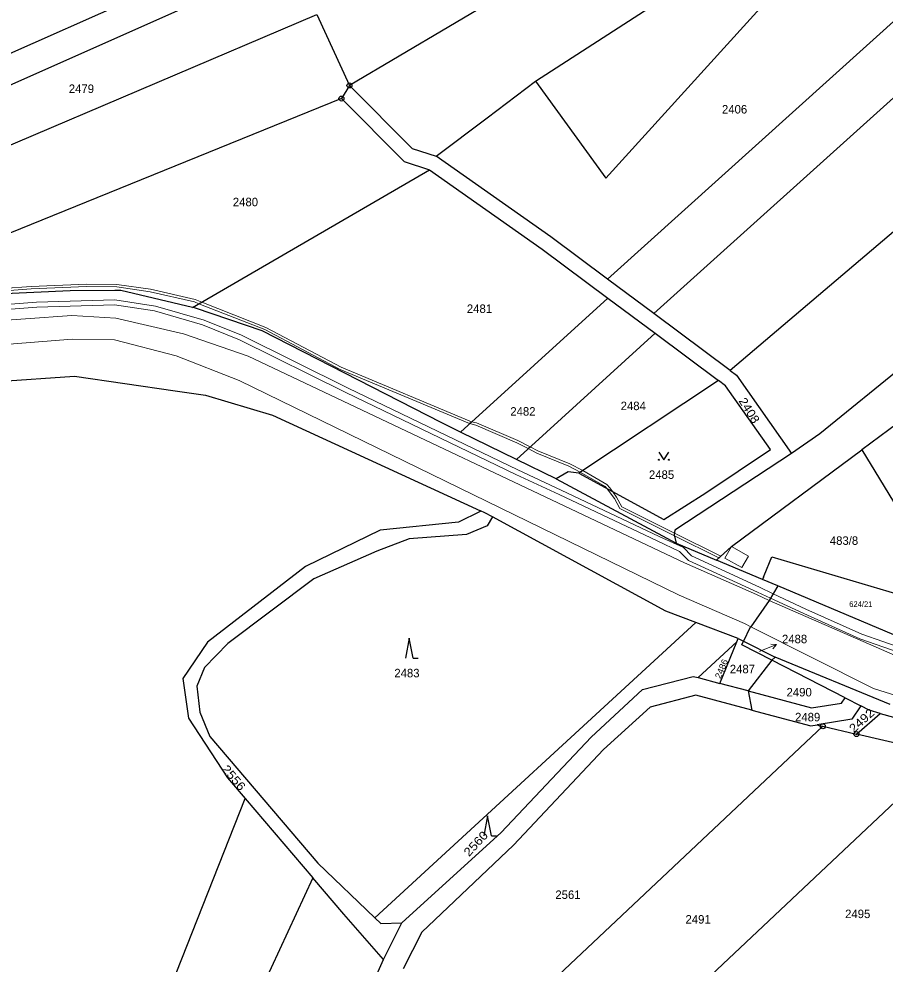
# Model space of a CAD drawing. Extents: x -606517 to -602431, y -1183120 to -1179397.
# Drawn here: x -605001.8 to -604828.2, y -1181046.7 to -1180857.3 of the extents above; entities that cross this region are included whole.
import ezdxf
from ezdxf.enums import TextEntityAlignment as Align

# ---------------------------------------------------------------- set-up
doc = ezdxf.new("R2010")
doc.units = 0
doc.header["$LTSCALE"] = 0.68
for name, color, linetype, lineweight in [('1', 7, 'Continuous', 25), ('13', 7, 'Continuous', 13), ('3', 7, 'Continuous', 25), ('4', 7, 'Continuous', 13), ('7', 7, 'Continuous', 13), ('8', 7, 'Continuous', 25)]:
    doc.layers.add(name, color=color, linetype=linetype, lineweight=lineweight)
doc.layers.add('2', color=7, linetype='Continuous')

msp = doc.modelspace()

# ---------------------------------------------------------------- linework, layer by layer
at = {"layer": '1'}
for p, q in [((-604864.72, -1180828.8), (-604935.53, -1180870.63)), ((-604883.82, -1180909.45), (-604798.46, -1180832.55)), ((-605066.61, -1180892.1), (-604946.99, -1180839.11)), ((-604874.53, -1180916.36), (-604790.07, -1180840.29)), ((-604945.04, -1180844.43), (-605064.46, -1180897.79)), ((-604898.22, -1180869.74), (-604864.02, -1180847.64)), ((-604884.17, -1180889.23), (-604851.96, -1180853.72)), ((-605061.96, -1180907.49), (-604942.1, -1180856.39)), ((-604942.1, -1180856.39), (-604935.53, -1180870.63)), ((-604907.94, -1180877.1), (-604898.22, -1180869.74)), ((-604898.22, -1180869.74), (-604884.17, -1180889.23)), ((-604935.53, -1180870.63), (-604937.14, -1180873.25)), ((-604935.53, -1180870.63), (-604922.99, -1180883.26)), ((-604937.14, -1180873.25), (-605039.85, -1180914.88)), ((-604937.14, -1180873.25), (-604924.6, -1180885.89)), ((-604918.14, -1180884.81), (-604907.94, -1180877.1)), ((-604922.99, -1180883.26), (-604918.14, -1180884.81)), ((-604895.17, -1180901), (-604918.14, -1180884.81)), ((-604924.6, -1180885.89), (-604919.49, -1180887.53)), ((-604966.98, -1180915.13), (-604919.49, -1180887.53)), ((-604919.49, -1180887.53), (-604896.93, -1180903.43)), ((-604812.16, -1180887.79), (-604859.22, -1180927.76)), ((-604883.82, -1180909.45), (-604895.17, -1180901)), ((-604896.93, -1180903.43), (-604883.73, -1180913.25)), ((-604874.53, -1180916.36), (-604883.82, -1180909.45)), ((-604991.55, -1180911.78), (-605019.29, -1180913.13)), ((-604982.55, -1180911.73), (-604991.55, -1180911.78)), ((-604981.39, -1180911.72), (-604982.55, -1180911.73)), ((-604966.98, -1180915.13), (-604981.39, -1180911.72)), ((-604913.3, -1180940.09), (-604883.73, -1180913.25)), ((-604883.73, -1180913.25), (-604874.25, -1180920.31)), ((-604806.84, -1180912.52), (-604841.26, -1180940.43)), ((-604966.4, -1180915.27), (-604966.98, -1180915.13)), ((-604953.06, -1180919.8), (-604966.4, -1180915.27)), ((-604859.22, -1180927.76), (-604874.53, -1180916.36)), ((-604798.64, -1180918.27), (-604832.85, -1180943.64)), ((-604917.16, -1180938.2), (-604953.06, -1180919.8)), ((-604874.25, -1180920.31), (-604902.08, -1180945.57)), ((-604874.25, -1180920.31), (-604861.56, -1180929.75)), ((-605009.45, -1180930.2), (-604990.65, -1180928.92)), ((-604990.65, -1180928.92), (-604970.51, -1180931.82)), ((-604859.22, -1180927.76), (-604857.95, -1180928.7)), ((-604857.95, -1180928.7), (-604846.92, -1180944.41)), ((-604861.56, -1180929.75), (-604889.57, -1180948.36)), ((-604860.13, -1180930.82), (-604861.56, -1180929.75)), ((-604851.14, -1180943.62), (-604860.13, -1180930.82)), ((-604970.51, -1180931.82), (-604964.37, -1180932.7)), ((-604964.37, -1180932.7), (-604950.98, -1180936.72)), ((-604950.98, -1180936.72), (-604909.28, -1180955.9)), ((-604913.3, -1180940.09), (-604917.16, -1180938.2)), ((-604902.08, -1180945.57), (-604913.3, -1180940.09)), ((-604841.26, -1180940.43), (-604846.92, -1180944.41)), ((-604864.12, -1180952.26), (-604851.14, -1180943.62)), ((-604858.98, -1180963.01), (-604832.85, -1180943.64)), ((-604832.85, -1180943.64), (-604824.77, -1180956.82)), ((-604894.13, -1180949.46), (-604902.08, -1180945.57)), ((-604846.92, -1180944.41), (-604870.34, -1180959.77)), ((-604891.7, -1180948.08), (-604894.13, -1180949.46)), ((-604894.13, -1180949.46), (-604870.06, -1180962.35)), ((-604889.57, -1180948.36), (-604891.7, -1180948.08)), ((-604889.57, -1180948.36), (-604872.52, -1180957.6)), ((-604872.52, -1180957.6), (-604864.12, -1180952.26)), ((-604909.35, -1180956.04), (-604913.68, -1180958.16)), ((-604909.28, -1180955.9), (-604909.35, -1180956.04)), ((-604908.42, -1180956.29), (-604909.28, -1180955.9)), ((-604906.89, -1180957.12), (-604908.42, -1180956.29)), ((-604906.89, -1180957.12), (-604907.93, -1180958.9)), ((-604872.09, -1180976), (-604906.89, -1180957.12)), ((-604913.68, -1180958.16), (-604929.38, -1180959.74)), ((-604907.93, -1180958.9), (-604912.09, -1180960.62)), ((-604929.38, -1180959.74), (-604944.32, -1180967.05)), ((-604912.09, -1180960.62), (-604923.56, -1180961.53)), ((-604870.34, -1180959.77), (-604870.42, -1180960.73)), ((-604870.42, -1180960.73), (-604870.06, -1180962.35)), ((-604923.56, -1180961.53), (-604930.03, -1180963.94)), ((-604870.06, -1180962.35), (-604861.98, -1180965.76)), ((-604861.98, -1180965.76), (-604858.98, -1180963.01)), ((-604930.03, -1180963.94), (-604942.7, -1180969.52)), ((-604852.72, -1180969.66), (-604861.98, -1180965.76)), ((-604852.38, -1180968.84), (-604850.83, -1180965.08)), ((-604850.83, -1180965.08), (-604813.29, -1180976.25)), ((-604944.32, -1180967.05), (-604963.99, -1180982.21)), ((-604942.7, -1180969.52), (-604959.95, -1180982.48)), ((-604852.52, -1180969.18), (-604852.72, -1180969.66)), ((-604849.66, -1180970.95), (-604852.72, -1180969.66)), ((-604852.52, -1180969.18), (-604852.38, -1180968.84)), ((-604849.66, -1180970.95), (-604851.38, -1180973.89)), ((-604825.12, -1180981.3), (-604849.66, -1180970.95)), ((-604851.38, -1180973.89), (-604855.08, -1180979.12)), ((-604866.12, -1180978.25), (-604872.09, -1180976)), ((-604866.12, -1180978.25), (-604930.42, -1181037.48)), ((-604857.58, -1180981.47), (-604866.12, -1180978.25)), ((-604855.24, -1180979.35), (-604856.52, -1180982.01)), ((-604855.08, -1180979.12), (-604855.24, -1180979.35)), ((-604857.86, -1180982.17), (-604857.58, -1180981.47)), ((-604857.58, -1180981.47), (-604856.52, -1180982.01)), ((-604963.99, -1180982.21), (-604968.92, -1180989.51)), ((-604959.95, -1180982.48), (-604964.57, -1180987.26)), ((-604865.63, -1180989.32), (-604857.86, -1180982.17)), ((-604861.28, -1180990.48), (-604857.86, -1180982.17)), ((-604856.87, -1180982.75), (-604856.52, -1180982.01)), ((-604850.87, -1180985.83), (-604856.87, -1180982.75)), ((-604856.52, -1180982.01), (-604850.17, -1180985.22)), ((-604850.17, -1180985.22), (-604850.87, -1180985.83)), ((-604827.14, -1180994.71), (-604850.17, -1180985.22)), ((-604964.57, -1180987.26), (-604966.12, -1180991.02)), ((-604850.87, -1180985.83), (-604855.63, -1180991.99)), ((-604836.18, -1180993.39), (-604850.87, -1180985.83)), ((-604968.92, -1180989.51), (-604967.79, -1180997.44)), ((-604876.8, -1180991.7), (-604866.61, -1180989.06)), ((-604866.61, -1180989.06), (-604865.63, -1180989.32)), ((-604865.63, -1180989.32), (-604861.28, -1180990.48)), ((-604966.12, -1180991.02), (-604965.56, -1180996.27)), ((-604855.63, -1180991.99), (-604861.28, -1180990.48)), ((-604887.08, -1181001.22), (-604876.8, -1180991.7)), ((-604866.11, -1180992.82), (-604875.28, -1180995.24)), ((-604854.87, -1180995.81), (-604866.11, -1180992.82)), ((-604855.63, -1180991.99), (-604842.88, -1180995.39)), ((-604855.63, -1180991.99), (-604854.87, -1180995.81)), ((-604875.28, -1180995.24), (-604884.61, -1181003.71)), ((-604842.88, -1180995.39), (-604836.89, -1180994.45)), ((-604836.89, -1180994.45), (-604836.18, -1180993.39)), ((-604836.18, -1180993.39), (-604833.05, -1180995)), ((-604833.05, -1180995), (-604834.83, -1180997.67)), ((-604831.37, -1180995.86), (-604833.05, -1180995)), ((-604965.56, -1180996.27), (-604963.5, -1181001.09)), ((-604854.87, -1180995.81), (-604843.07, -1180998.96)), ((-604833.9, -1181000.64), (-604829.17, -1180996.48)), ((-604829.17, -1180996.48), (-604831.37, -1180995.86)), ((-604829.17, -1180996.48), (-604803.37, -1181003.79)), ((-604967.79, -1180997.44), (-604959.98, -1181009.37)), ((-604843.07, -1180998.96), (-604841.8, -1180998.76)), ((-604834.83, -1180997.67), (-604841.8, -1180998.76)), ((-604841.8, -1180998.76), (-604841.43, -1180998.89)), ((-604841.43, -1180998.89), (-604840.66, -1180999.07)), ((-604947.06, -1181099.25), (-604840.66, -1180999.07)), ((-604840.66, -1180999.07), (-604833.9, -1181000.64)), ((-604820.91, -1181003.67), (-604833.9, -1181000.64)), ((-604963.5, -1181001.09), (-604941.86, -1181026.53)), ((-604905.13, -1181020.39), (-604887.08, -1181001.22)), ((-604953.33, -1181133.92), (-604815.93, -1181004.56)), ((-604884.61, -1181003.71), (-604902.68, -1181022.89)), ((-604959.98, -1181009.37), (-604956.44, -1181013.52)), ((-604995.84, -1181113.11), (-604956.44, -1181013.52)), ((-604956.44, -1181013.52), (-604942.89, -1181029.42)), ((-604925.04, -1181038.48), (-604905.13, -1181020.39)), ((-604902.68, -1181022.89), (-604921.05, -1181040.36)), ((-604941.86, -1181026.53), (-604930.42, -1181037.48)), ((-604942.89, -1181029.42), (-604958.82, -1181063.74)), ((-604936.67, -1181036.71), (-604942.89, -1181029.42)), ((-604928.68, -1181045.8), (-604936.67, -1181036.71)), ((-604930.42, -1181037.48), (-604929.25, -1181038.6)), ((-604929.25, -1181038.6), (-604925.04, -1181038.48)), ((-604928.68, -1181045.8), (-604925.04, -1181038.48)), ((-604921.05, -1181040.36), (-604924.8, -1181047.67)), ((-604940.36, -1181071.47), (-604928.68, -1181045.8))]:
    msp.add_line(p, q, dxfattribs=at)
at = {"layer": '13'}
for points in [[(-604965.16, -1180914.07), (-604966.44, -1180913.52), (-604975.42, -1180911.48), (-604982.15, -1180910.49), (-604988.28, -1180910.43), (-604999.37, -1180910.91), (-605010.75, -1180911.74), (-605017.08, -1180912.29), (-605027.29, -1180913.7), (-605032.77, -1180914.28), (-605019.29, -1180913.13), (-605017.02, -1180912.79), (-605010.71, -1180912.24), (-604999.35, -1180911.41), (-604988.28, -1180910.93), (-604982.19, -1180910.99), (-604975.52, -1180911.98), (-604966.58, -1180914), (-604965.71, -1180914.39)], [(-604952.53, -1180919.57), (-604937.39, -1180927.53), (-604911.45, -1180938.41), (-604911.04, -1180938.04), (-604937.19, -1180927.07), (-604952.29, -1180919.13), (-604965.16, -1180914.07), (-604965.71, -1180914.39)], [(-604911.45, -1180938.41), (-604910.22, -1180938.73), (-604902.01, -1180942.26), (-604899.72, -1180943.42), (-604899.32, -1180943.06), (-604901.79, -1180941.8), (-604910.06, -1180938.25), (-604911.04, -1180938.04)], [(-604888.77, -1180947.83), (-604891.36, -1180946.49), (-604897.74, -1180943.87), (-604899.32, -1180943.06), (-604899.72, -1180943.42), (-604897.94, -1180944.33), (-604891.58, -1180946.95), (-604889.27, -1180948.16)], [(-604889.27, -1180948.16), (-604884.27, -1180951.03), (-604883.85, -1180951.46), (-604882.4, -1180953.4), (-604881.33, -1180955.45), (-604870.38, -1180960.91), (-604870.42, -1180960.73), (-604870.39, -1180960.34), (-604880.95, -1180955.09), (-604881.98, -1180953.14), (-604882.77, -1180952.05), (-604883.32, -1180951.29), (-604883.95, -1180950.63), (-604888.77, -1180947.83)], [(-604870.38, -1180960.91), (-604861.51, -1180965.33), (-604861.1, -1180964.95), (-604870.39, -1180960.34), (-604870.42, -1180960.73)]]:
    msp.add_lwpolyline(points, close=True, dxfattribs=at)
for points in [[(-604820.21, -1180985.01), (-604832.81, -1180980.61), (-604844.02, -1180975.57), (-604850.58, -1180972.52), (-604853.36, -1180971.22), (-604866.94, -1180964.89), (-604868.57, -1180963.23), (-604873.46, -1180961.02), (-604893.1, -1180951.74), (-604901.76, -1180947.69), (-604935.81, -1180931.3), (-604957.19, -1180920.7), (-604964.68, -1180917.68), (-604974.39, -1180914.85), (-604982.59, -1180913.62), (-604998.29, -1180914.05), (-605009.54, -1180914.93)], [(-605009.47, -1180915.93), (-604998.24, -1180915.05), (-604982.65, -1180914.62), (-604974.61, -1180915.83), (-604965, -1180918.62), (-604957.6, -1180921.62), (-604936.26, -1180932.2), (-604902.18, -1180948.59), (-604893.51, -1180952.64), (-604873.88, -1180961.92), (-604869.36, -1180964.04), (-604867.57, -1180965.87), (-604853.76, -1180972.2), (-604851.1, -1180973.42), (-604844.44, -1180976.47), (-604833.19, -1180981.53), (-604820.51, -1180985.97)]]:
    msp.add_lwpolyline(points, dxfattribs=at)
at = {"layer": '3'}
for p, q in [((-604922.79, -1180985.43), (-604921.794, -1180985.43)), ((-604907.08, -1181021.02), (-604906.084, -1181021.02))]:
    msp.add_line(p, q, dxfattribs=at)
for points in [[(-604873.5, -1180944.159), (-604872.5, -1180945.66), (-604871.5, -1180944.159)], [(-604922.79, -1180985.43), (-604923.54, -1180981.43), (-604924.29, -1180985.43)], [(-604907.08, -1181021.02), (-604907.83, -1181017.02), (-604908.58, -1181021.02)]]:
    msp.add_lwpolyline(points, dxfattribs=at)
for centre in [(-604873.5, -1180945.6595), (-604871.5, -1180945.6595)]:
    msp.add_circle(centre, 0.1, dxfattribs=at)
at = {"layer": '4'}
for p, q in [((-604860.28, -1180965.36), (-604858.98, -1180963.01)), ((-604858.98, -1180963.01), (-604855.54, -1180964.97)), ((-604868.36, -1180966.28), (-604853.94, -1180972.63)), ((-604856.86, -1180967.26), (-604860.28, -1180965.36)), ((-604855.54, -1180964.97), (-604856.86, -1180967.26)), ((-604856.35, -1180978.48), (-604869.45, -1180972.79)), ((-604853.94, -1180972.63), (-604851.38, -1180973.89)), ((-604851.38, -1180973.89), (-604825.21, -1180985.29))]:
    msp.add_line(p, q, dxfattribs=at)
for points in [[(-605019.1, -1180918.73), (-604991.17, -1180916.75), (-604982.34, -1180917.27), (-604968.84, -1180920.41), (-604955.87, -1180924.9), (-604868.36, -1180966.28)], [(-605262.69, -1180946.11), (-605224.79, -1180940.54), (-605180.08, -1180937.13), (-605018.93, -1180923.69), (-604991.13, -1180921.45)], [(-604970.3, -1180924.8), (-604982.63, -1180921.64), (-604991.13, -1180921.45)], [(-604869.45, -1180972.79), (-604957.65, -1180929.78), (-604970.3, -1180924.8)], [(-604856.35, -1180978.48), (-604855.08, -1180979.12), (-604830.49, -1180991.47)], [(-604830.49, -1180991.47), (-604806.89, -1180998.93), (-604783.79, -1181002.75), (-604737.36, -1181005.03)]]:
    msp.add_lwpolyline(points, dxfattribs=at)
at = {"layer": '7'}
msp.add_line((-604849.918, -1180982.706), (-604851.034, -1180982.617), dxfattribs=at)
msp.add_lwpolyline([(-604853.36, -1180984.1), (-604852.7, -1180983.83), (-604849.918, -1180982.706), (-604850.658, -1180983.545)], dxfattribs=at)
at = {"layer": '8'}
for centre, radius in [((-604935.53, -1180870.6299), 0.5), ((-604935.53, -1180870.6299), 0.0303), ((-604937.14, -1180873.2499), 0.5), ((-604937.14, -1180873.2499), 0.0303), ((-604840.66, -1180999.0699), 0.5), ((-604840.66, -1180999.0699), 0.0303), ((-604833.9, -1181000.6399), 0.5), ((-604833.9, -1181000.6399), 0.0303)]:
    msp.add_circle(centre, radius, dxfattribs=at)

# ---------------------------------------------------------------- texts
at = {"layer": '2'}
for s, p in [('2479', (-604991.8, -1180872.135)), ('2406', (-604860.86, -1180876.255)), ('2480', (-604958.92, -1180894.835)), ('2481', (-604912, -1180916.225)), ('2484', (-604881.17, -1180935.705)), ('2482', (-604903.29, -1180936.805)), ('2485', (-604875.5, -1180949.485)), ('483/8', (-604839.24, -1180962.705)), ('2488', (-604848.83, -1180982.425)), ('2483', (-604926.54, -1180989.255)), ('2487', (-604859.29, -1180988.445)), ('2490', (-604847.91, -1180993.085)), ('2489', (-604846.21, -1180998.075)), ('2561', (-604894.26, -1181033.675)), ('2491', (-604868.17, -1181038.615)), ('2495', (-604836.17, -1181037.515))]:
    msp.add_text(s, height=1.7, dxfattribs=at).set_placement(p)
for s, height, rotation, width, p in [('2408', 1.7, 302, 1.1, (-604857.58, -1180933.855)), ('2486', 1.28, 67, 1.05, (-604861.155, -1180989.645)), ('2492', 1.7, 42, 1.15, (-604834.435, -1181000.485)), ('2556', 1.7, 310, 1.15, (-604961.235, -1181007.703)), ('2560', 1.7, 47, 1.15, (-604911.569, -1181025.299))]:
    msp.add_text(s, height=height, rotation=rotation, dxfattribs=dict(at, width=width)).set_placement(p)
msp.add_text('624/21', height=1.14, dxfattribs=at).set_placement((-604833.019, -1180975.16), align=Align.CENTER)

doc.saveas('drawing.dxf')
